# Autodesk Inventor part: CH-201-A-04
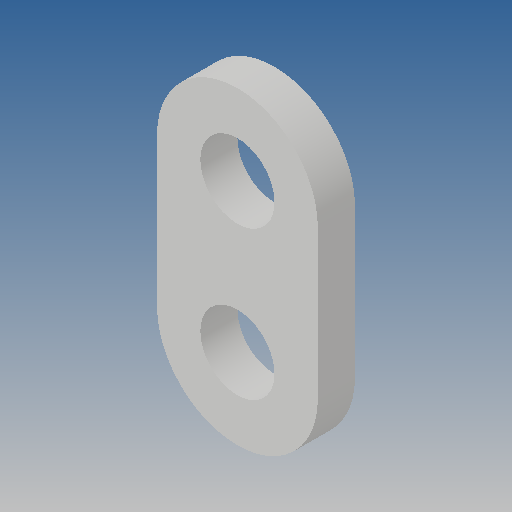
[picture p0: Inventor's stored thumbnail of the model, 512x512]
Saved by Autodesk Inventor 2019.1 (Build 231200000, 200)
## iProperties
Created: 2012-09
Part Number: CH-201-A-04
Material: Ogólny
Document SubType Name: Modeling
Designer: CADENGINEERING4
Density: 1 g/cm^3
Appearance: Domyślna
Author: CADENGINEERING4
Revision Number: ÈÎºÎ
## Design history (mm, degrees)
feature "À­Éì1"
node "Bryła1"
